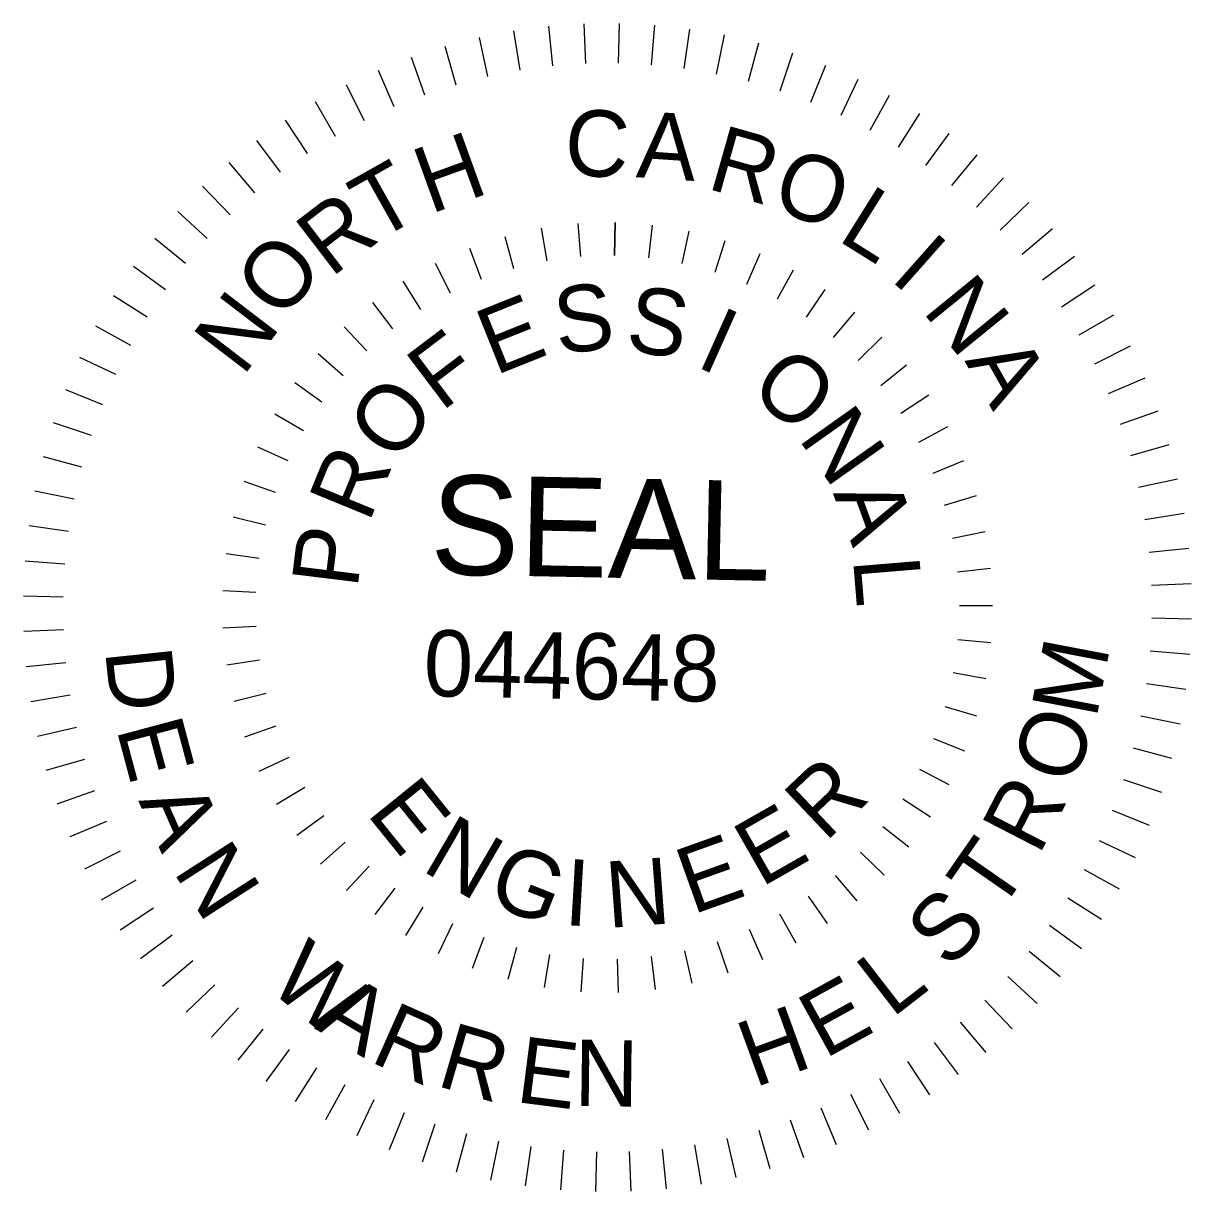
# Model space of a CAD drawing. Extents: x 0 to 4772457, y -312190 to 1506.
# Drawn here: x 3.293 to 3.4147, y 1.5709 to 1.6926 of the extents above; entities that cross this region are included whole.
import ezdxf

# ---------------------------------------------------------------- set-up
doc = ezdxf.new("R2010")
doc.units = 0
doc.layers.add('Phasing Diagram CELL', color=7, linetype='Continuous')

msp = doc.modelspace()

# ---------------------------------------------------------------- linework, layer by layer
at = {"layer": 'Phasing Diagram CELL'}
for p, q in [((3.34406, 1.69181), (3.34473, 1.68772)), ((3.34771, 1.69229), (3.34812, 1.68816)), ((3.35137, 1.69255), (3.35154, 1.68841)), ((3.35505, 1.69259), (3.35497, 1.68844)), ((3.35873, 1.6924), (3.3584, 1.68827)), ((3.36238, 1.692), (3.3618, 1.68789)), ((3.34046, 1.69111), (3.34136, 1.68706)), ((3.366, 1.69138), (3.36518, 1.68731)), ((3.33689, 1.6902), (3.33805, 1.6862)), ((3.36958, 1.69053), (3.36851, 1.68653)), ((3.37311, 1.68948), (3.37179, 1.68553)), ((3.33339, 1.68907), (3.33479, 1.68515)), ((3.37655, 1.68821), (3.375, 1.68436)), ((3.32997, 1.68772), (3.33159, 1.68391)), ((3.32663, 1.68618), (3.32849, 1.68247)), ((3.37992, 1.68673), (3.37815, 1.68298)), ((3.38319, 1.68506), (3.38119, 1.68142)), ((3.32339, 1.68444), (3.32547, 1.68085)), ((3.32027, 1.6825), (3.32256, 1.67904)), ((3.38636, 1.68319), (3.38414, 1.67968)), ((3.38941, 1.68113), (3.38699, 1.67777)), ((3.31727, 1.68038), (3.31976, 1.67707)), ((3.39232, 1.6789), (3.3897, 1.67568)), ((3.31439, 1.67808), (3.31708, 1.67493)), ((3.3951, 1.67648), (3.39229, 1.67343)), ((3.31167, 1.67562), (3.31454, 1.67263)), ((3.39773, 1.67391), (3.39474, 1.67104)), ((3.3091, 1.67299), (3.31214, 1.67018)), ((3.34692, 1.67125), (3.34751, 1.66784)), ((3.35076, 1.67173), (3.35103, 1.66829)), ((3.35464, 1.67184), (3.35457, 1.66839)), ((3.35457, 1.66839), (3.35464, 1.67184)), ((3.35851, 1.67158), (3.35811, 1.66815)), ((3.40019, 1.67119), (3.39704, 1.6685)), ((3.30668, 1.67021), (3.3099, 1.66759)), ((3.34314, 1.6704), (3.34406, 1.66706)), ((3.36233, 1.67094), (3.3616, 1.66756)), ((3.36607, 1.66994), (3.36502, 1.66665)), ((3.33946, 1.66918), (3.3407, 1.66595)), ((3.33591, 1.66762), (3.33745, 1.66453)), ((3.36971, 1.66858), (3.36834, 1.6654)), ((3.4025, 1.66831), (3.39918, 1.66582)), ((3.30445, 1.6673), (3.30781, 1.66487)), ((3.37319, 1.66688), (3.37153, 1.66385)), ((3.33253, 1.66572), (3.33437, 1.66279)), ((3.40461, 1.66531), (3.40116, 1.66302)), ((3.30239, 1.66425), (3.3059, 1.66203)), ((3.37649, 1.66485), (3.37454, 1.66199)), ((3.32935, 1.6635), (3.33146, 1.66076)), ((3.37958, 1.66251), (3.37736, 1.65985)), ((3.40655, 1.66219), (3.40296, 1.66011)), ((3.30052, 1.66108), (3.30416, 1.65908)), ((3.3264, 1.66099), (3.32877, 1.65846)), ((3.38243, 1.65988), (3.37996, 1.65745)), ((3.40829, 1.65895), (3.40458, 1.65709)), ((3.29885, 1.65781), (3.3026, 1.65603)), ((3.3237, 1.6582), (3.3263, 1.65592)), ((3.38501, 1.65699), (3.38233, 1.65481)), ((3.40983, 1.65561), (3.40602, 1.65398)), ((3.29737, 1.65444), (3.30122, 1.65289)), ((3.32129, 1.65517), (3.32409, 1.65315)), ((3.38731, 1.65387), (3.38442, 1.65195)), ((3.31918, 1.65192), (3.32216, 1.65018)), ((3.41118, 1.65218), (3.40727, 1.65079)), ((3.2961, 1.65099), (3.30004, 1.64968)), ((3.38928, 1.65054), (3.38623, 1.64891)), ((3.31739, 1.64848), (3.32053, 1.64704)), ((3.41231, 1.64869), (3.40832, 1.64753)), ((3.29505, 1.64746), (3.29905, 1.6464)), ((3.39094, 1.64702), (3.38774, 1.64571)), ((3.31595, 1.64488), (3.31922, 1.64375)), ((3.41322, 1.64512), (3.40918, 1.64422)), ((3.2942, 1.64389), (3.29827, 1.64306)), ((3.39224, 1.64337), (3.38892, 1.64237)), ((3.31485, 1.64117), (3.31822, 1.64035)), ((3.41392, 1.64152), (3.40983, 1.64085)), ((3.29358, 1.64027), (3.29769, 1.63969)), ((3.39318, 1.63961), (3.38979, 1.63893)), ((3.31413, 1.63736), (3.31755, 1.63688)), ((3.4144, 1.63787), (3.41028, 1.63746)), ((3.29318, 1.63661), (3.29731, 1.63628)), ((3.39376, 1.63578), (3.39032, 1.63543)), ((3.31377, 1.6335), (3.31722, 1.63334)), ((3.35101, 1.63413), (3.35101, 1.63413)), ((3.41466, 1.63421), (3.41052, 1.63404)), ((3.29299, 1.63294), (3.29714, 1.63286)), ((3.39396, 1.63191), (3.39051, 1.63189)), ((3.31378, 1.62962), (3.31723, 1.6298)), ((3.4147, 1.63053), (3.41055, 1.63061)), ((3.29303, 1.62926), (3.29717, 1.62943)), ((3.39379, 1.62804), (3.39035, 1.62835)), ((3.31418, 1.62576), (3.31759, 1.62628)), ((3.41452, 1.62685), (3.41038, 1.62718)), ((3.29329, 1.62559), (3.29742, 1.62601)), ((3.38987, 1.62497), (3.39327, 1.62433)), ((3.41411, 1.6232), (3.41001, 1.62378)), ((3.29377, 1.62195), (3.29786, 1.62262)), ((3.31494, 1.62196), (3.31829, 1.6228)), ((3.39234, 1.62043), (3.38902, 1.6214)), ((3.41349, 1.61958), (3.40942, 1.6204)), ((3.29447, 1.61834), (3.29852, 1.61925)), ((3.31606, 1.61825), (3.31932, 1.61941)), ((3.39107, 1.61676), (3.38786, 1.61805)), ((3.41265, 1.616), (3.40864, 1.61707)), ((3.29538, 1.61478), (3.29938, 1.61593)), ((3.31754, 1.61467), (3.32067, 1.61614)), ((3.38944, 1.61325), (3.38638, 1.61484)), ((3.29651, 1.61128), (3.30043, 1.61268)), ((3.31935, 1.61125), (3.32233, 1.61301)), ((3.41159, 1.61247), (3.40765, 1.61379)), ((3.3875, 1.6099), (3.3846, 1.61177)), ((3.41032, 1.60903), (3.40647, 1.61058)), ((3.29786, 1.60786), (3.30167, 1.60948)), ((3.32149, 1.60801), (3.32428, 1.61005)), ((3.38523, 1.60675), (3.38253, 1.6089)), ((3.32394, 1.605), (3.32651, 1.6073)), ((3.40884, 1.60566), (3.4051, 1.60743)), ((3.2994, 1.60452), (3.30311, 1.60638)), ((3.38267, 1.60384), (3.38019, 1.60624)), ((3.32665, 1.60224), (3.329, 1.60478)), ((3.40717, 1.60239), (3.40353, 1.60439)), ((3.30114, 1.60128), (3.30473, 1.60336)), ((3.37985, 1.60119), (3.37761, 1.60382)), ((3.32963, 1.59976), (3.33171, 1.60251)), ((3.33283, 1.59757), (3.33464, 1.60051)), ((3.37678, 1.59882), (3.3748, 1.60165)), ((3.4053, 1.59922), (3.4018, 1.60144)), ((3.30308, 1.59816), (3.30654, 1.60044)), ((3.3735, 1.59676), (3.3718, 1.59978)), ((3.33623, 1.5957), (3.33774, 1.59881)), ((3.37003, 1.59503), (3.36863, 1.59819)), ((3.40324, 1.59617), (3.39988, 1.59859)), ((3.3052, 1.59516), (3.30851, 1.59764)), ((3.33979, 1.59416), (3.341, 1.5974)), ((3.36641, 1.59363), (3.36532, 1.59692)), ((3.34435, 1.59633), (3.34345, 1.59298)), ((3.36267, 1.5926), (3.36191, 1.59598)), ((3.40101, 1.59326), (3.39779, 1.59588)), ((3.3075, 1.59228), (3.31065, 1.59497)), ((3.34727, 1.59216), (3.34783, 1.59557)), ((3.35112, 1.59171), (3.35135, 1.59516)), ((3.35499, 1.59163), (3.35489, 1.59509)), ((3.35885, 1.59193), (3.35842, 1.59536)), ((3.3986, 1.59048), (3.39555, 1.59329)), ((3.30996, 1.58956), (3.31295, 1.59243)), ((3.39602, 1.58785), (3.39315, 1.59084)), ((3.31259, 1.58698), (3.3154, 1.59003)), ((3.3933, 1.58539), (3.39061, 1.58854)), ((3.31537, 1.58457), (3.31799, 1.58779)), ((3.39042, 1.58308), (3.38793, 1.5864)), ((3.31828, 1.58234), (3.32071, 1.5857)), ((3.32133, 1.58028), (3.32355, 1.58378)), ((3.38742, 1.58097), (3.38514, 1.58442)), ((3.3843, 1.57903), (3.38222, 1.58262)), ((3.3245, 1.57841), (3.3265, 1.58204)), ((3.32777, 1.57674), (3.32955, 1.58048)), ((3.38106, 1.57729), (3.3792, 1.581)), ((3.33114, 1.57526), (3.33269, 1.57911)), ((3.37772, 1.57575), (3.3761, 1.57956)), ((3.33459, 1.57399), (3.3359, 1.57793)), ((3.3743, 1.5744), (3.3729, 1.57831)), ((3.33812, 1.57293), (3.33918, 1.57694)), ((3.34169, 1.57209), (3.34252, 1.57615)), ((3.36724, 1.57236), (3.36633, 1.5764)), ((3.3708, 1.57327), (3.36965, 1.57726)), ((3.34531, 1.57147), (3.34589, 1.57557)), ((3.34897, 1.57106), (3.3493, 1.5752)), ((3.35264, 1.57088), (3.35272, 1.57503)), ((3.35632, 1.57092), (3.35615, 1.57506)), ((3.35998, 1.57118), (3.35957, 1.5753)), ((3.36363, 1.57166), (3.36296, 1.57575))]:
    msp.add_line(p, q, dxfattribs=at)

# ---------------------------------------------------------------- texts
for s, height, rotation, p in [('C', 0.00691, 356.2217, (3.34921, 1.67686)), ('A', 0.00691, 356.2217, (3.35676, 1.67657)), ('H', 0.00691, 19.9324, (3.33538, 1.67269)), ('R', 0.00691, 344.2124, (3.36406, 1.67541)), ('T', 0.00691, 29.3644, (3.32975, 1.6698)), ('O', 0.00691, 341.1556, (3.37071, 1.67329)), ('L', 0.00691, 328.0193, (3.37768, 1.67007)), ('R', 0.00691, 37.5253, (3.32503, 1.66602)), ('O', 0.00691, 50.5821, (3.31994, 1.66147)), ('I', 0.00691, 318.4439, (3.38317, 1.66595)), ('N', 0.00691, 309.1494, (3.38656, 1.66263)), ('S', 0.00691, 6.5129, (3.34867, 1.65811)), ('S', 0.00691, 351.2166, (3.35558, 1.65855)), ('N', 0.00691, 52.5415, (3.31585, 1.65571)), ('E', 0.00691, 21.8091, (3.34213, 1.65587)), ('I', 0.00691, 335.9204, (3.36289, 1.65691)), ('F', 0.00691, 37.1054, (3.33653, 1.65207)), ('O', 0.00691, 320.6242, (3.36841, 1.65411)), ('A', 0.00691, 299.3819, (3.39102, 1.65744)), ('O', 0.00691, 52.4016, (3.33182, 1.64659)), ('N', 0.00691, 305.3279, (3.37364, 1.64938)), ('R', 0.00691, 67.6979, (3.32897, 1.64044)), ('SEAL', 0.010372, 358.8648, (3.33533, 1.63521)), ('A', 0.00691, 290.0317, (3.37732, 1.64365)), ('P', 0.00691, 82.9941, (3.32779, 1.63361)), ('L', 0.00691, 274.7354, (3.37942, 1.63677)), ('044648', 0.006909, 358.8648, (3.33465, 1.62251)), ('M', 0.00691, 79.1773, (3.40477, 1.62004)), ('D', 0.00691, 275.9811, (3.3015, 1.62723)), ('E', 0.00691, 284.9836, (3.30266, 1.61913)), ('O', 0.00691, 71.1829, (3.40239, 1.61301)), ('R', 0.00691, 43.4297, (3.37651, 1.6072)), ('E', 0.00691, 308.9349, (3.32865, 1.61029)), ('R', 0.00691, 62.7337, (3.39878, 1.60579)), ('A', 0.00691, 293.8062, (3.30496, 1.61161)), ('E', 0.00691, 29.6586, (3.36983, 1.60252)), ('N', 0.00691, 329.7899, (3.33434, 1.60441)), ('E', 0.00691, 19.6727, (3.36269, 1.59971)), ('T', 0.00691, 55.228, (3.3946, 1.5997)), ('N', 0.00691, 302.6889, (3.30852, 1.60427)), ('G', 0.00691, 338.5562, (3.34104, 1.60104)), ('I', 0.00691, 356.651, (3.34922, 1.59866)), ('N', 0.00691, 4.2806, (3.3539, 1.59834)), ('S', 0.00691, 46.5552, (3.38946, 1.5939)), ('W', 0.00691, 320.3641, (3.31828, 1.59217)), ('L', 0.00691, 37.7626, (3.38347, 1.58889)), ('E', 0.00691, 28.88, (3.37646, 1.58466)), ('A', 0.00691, 329.3125, (3.32323, 1.58791)), ('R', 0.00691, 336.0279, (3.32895, 1.58448)), ('H', 0.00691, 19.9974, (3.36914, 1.58168)), ('R', 0.00691, 343.8077, (3.33587, 1.58195)), ('E', 0.00691, 352.7158, (3.34416, 1.58023)), ('N', 0.00691, 359.3001, (3.35036, 1.57981))]:
    msp.add_text(s, height=height, rotation=rotation, dxfattribs=at).set_placement(p)

doc.saveas('drawing.dxf')
